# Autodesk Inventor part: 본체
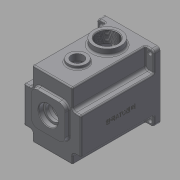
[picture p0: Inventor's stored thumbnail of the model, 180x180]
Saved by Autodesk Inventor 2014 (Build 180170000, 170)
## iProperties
Created: 2016-02
Part Number: 본체
Material: 일반
Document SubType Name: Modeling
Designer: mduedu
Density: 2.71 g/cm^3
Appearance: 기본값
Author: mduedu
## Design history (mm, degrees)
sketch "스케치1"
  geometry: L1 (-47, -47)-(47, -47); L2 (47, -47)-(47, 63); L3 (47, 63)-(-47, 63); L4 (-47, 63)-(-47, -47); 2 further points
  constraints: 8 end point, 2 parallel, 1 horizontal, 1 midpoint, 1 perpendicular, 1 vertical alignment
  dimensions: "d0" = 94 distance of L2.end L3.end; "d155" = 110 distance of L1.end L2.end; "d156" = 47 distance from line of L1 point (0, 0)
extrude "돌출1" new body sketch "스케치1" distance "d2" = 130; taper "d3" = 0 deg
sketch "스케치3"
  geometry: C1 r 40 at (0, 0); 1 further point
  constraints: 1 centre point, 1 coincident
  dimensions: "d9" = 80 diameter of C1
extrude "돌출3" cut sketch "스케치3" distance "d11" = 121; taper "d12" = 0 deg
sketch "스케치4"
  geometry: C1 r 21 at (0, 11); 1 further point
  constraints: 1 centre point, 1 vertical alignment
  dimensions: "d13" = 21 radius of C1; "d15" = 11 distance of point (0, 0) C1.centre
extrude "돌출4" join sketch "스케치4" distance "d16" = 7; taper "d17" = 0 deg
sketch "스케치5"
  geometry: C1 r 15 at (0, -20); 1 further point
  constraints: 1 centre point, 1 vertical alignment
  dimensions: "d18" = 15 radius of C1; "d20" = 20 distance of point (0, 0) C1.centre
extrude "돌출5" join sketch "스케치5" distance "d21" = 7; taper "d22" = 0 deg
sketch "스케치6"
  geometry: L1 (-28, -17)-(28, -17); L2 (28, -17)-(28, 39); L3 (28, 39)-(-28, 39); L4 (-28, 39)-(-28, -17); L5 (-28, -17)-(28, 39); L6 (28, -17)-(-28, 39); C1 r 28 at (0, 11); A1 r 21 centre (0, 11) between (8.978, -7.984) and (-8.978, -7.984) reference; 1 further point
  constraints: 12 end point, 2 midpoint, 2 parallel, 2 tangent, 1 centre point, 1 coincident, 1 horizontal, 1 perpendicular
  dimensions: "d23" = 56 diameter of C1
extrude "돌출6" join sketch "스케치6" distance "d25" = 7; taper "d26" = -3 deg
hole "구멍1" diameter "d29" = 35; stored, may be unused: countersink angle "d33" = 90 deg, drill point angle "d35" = 0 deg; dims "d27" = 10, "d28" = 10, "d30" = 6, "d31" = 4, "d32" = 2, "d34" = 10
hole "구멍2" diameter "d38" = 22; stored, may be unused: countersink angle "d42" = 90 deg, drill point angle "d44" = 0 deg; dims "d36" = 10, "d37" = 10, "d39" = 6, "d40" = 4, "d41" = 2, "d43" = 7
hole "구멍3" diameter "d47" = 19; stored, may be unused: countersink angle "d51" = 90 deg, drill point angle "d53" = 0 deg; dims "d45" = 10, "d46" = 10, "d48" = 6, "d49" = 4, "d50" = 2, "d52" = 1
hole "구멍4" diameter "d56" = 32; stored, may be unused: countersink angle "d60" = 90 deg, drill point angle "d62" = 0 deg; dims "d57" = 6, "d58" = 4, "d59" = 2, "d61" = 8, "d220" = 10, "d221" = 10
hole "구멍5" diameter "d65" = 25; stored, may be unused: countersink angle "d69" = 90 deg, drill point angle "d71" = 0 deg; dims "d63" = 10, "d64" = 10, "d66" = 6, "d67" = 4, "d68" = 2, "d70" = 8
fillet "모깎기2" dims "d73" = 0.3
fillet "모깎기3" dims "d74" = 2
chamfer "모따기1" distance "d75" = 1; stored, may be unused: second distance "d76" = 2, angle "d77" = 45 deg
fillet "모깎기4" dims "d78" = 3
sketch "스케치16"
  geometry: L1 (-23, 32.726)-(23, 32.726); L2 (23, 32.726)-(23, 53); L3 (23, 53)-(-23, 53); L4 (-23, 53)-(-23, 32.726); L5 (-47, 63)-(47, 63) reference; 3 further points
  constraints: 8 end point, 2 parallel, 1 horizontal, 1 midpoint, 1 perpendicular, 1 vertical alignment, 2 other
  dimensions: "d160" = 46 distance of L2.end L3.end; "d163" = 10 distance between parallel lines of L3 L5
extrude "돌출15" cut sketch "스케치16" stored distance "d164" = 10; taper "d165" = 0 deg
fillet "모깎기5" dims "d79" = 2
fillet "모깎기15" dims "d166" = 5
sketch "스케치7"
  geometry: L1 (-23, 48)-(-23, 35.228) reference; L2 (23, 35.228)-(23, 48) reference; L3 (18, 53)-(-18, 53) reference; L4 (47, 63)-(47, -47) reference; L5 (47, -47)-(-47, -47) reference; L6 (-47, -47)-(-47, 63) reference; L7 (-47, 63)-(47, 63) reference; L8 (-26, 48)-(-26, 35.228); L9 (26, 35.228)-(26, 48); L10 (18, 56)-(-18, 56); C1 r 43 at (0, 0); A1 r 5 centre (-18, 48) between (-18, 53) and (-23, 48) reference; A2 r 5 centre (-28, 35.228) between (-24.889, 31.314) and (-23, 35.228) reference; A3 r 40 centre (0, 0) between (-24.889, 31.314) and (24.889, 31.314) reference; A4 r 5 centre (28, 35.228) between (23, 35.228) and (24.889, 31.314) reference; A5 r 5 centre (18, 48) between (23, 48) and (18, 53) reference; A6 r 8 centre (-18, 48) between (-18, 56) and (-26, 48); A7 r 2 centre (-28, 35.228) between (-26.756, 33.662) and (-26, 35.228); A8 r 43 centre (0, 0) between (-26.756, 33.662) and (26.756, 33.662); A9 r 2 centre (28, 35.228) between (26, 35.228) and (26.756, 33.662); A10 r 8 centre (18, 48) between (26, 48) and (18, 56); 1 further point
  constraints: 10 point on circle, 6 centre point, 6 end point, 1 coincident, 7 other
  dimensions: "d80" = 86 diameter of C1; "d167" = 3 distance between parallel lines of L3 L10
extrude "돌출7" cut sketch "스케치7" distance "d83" = 9; taper "d84" = 0 deg
sketch "스케치8" dims "d168" = 36
  geometry: L1 (-36, 4)-(-39.799, 4); L2 (-36, -4)-(-39.799, -4); A1 r 4 centre (-36, 0) between (-36, 4) and (-36, -4); A2 r 40 centre (0, 0) between (-24.889, 31.314) and (24.889, 31.314) reference; A3 r 40 centre (0, 0) between (-39.799, 4) and (-39.799, -4); 2 further points
  constraints: 5 point on circle, 4 end point, 2 centre point, 2 coincident, 2 horizontal alignment, 2 tangent, 1 horizontal, 1 parallel, 2 other
  dimensions: "d169" = 4 radius of A1
extrude "돌출9" join sketch "스케치8" stored distance "d89" = 9; taper "d90" = 0 deg
fillet "모깎기6" dims "d91" = 3.5
node "작업 평면1"
sketch "스케치9"
  geometry: L1 (47, 63)-(33, 63); L2 (33, 63)-(33, 30); L3 (33, 30)-(47, 30); L4 (47, 30)-(47, 63); L5 (47, 63)-(-47, 63) reference; L6 (47, -47)-(47, 63) reference; A1 r 40 centre (0, 0) between (-39.148, -8.214) and (39.148, -8.214) reference; 1 further point
  constraints: 8 end point, 2 parallel, 1 coincident, 1 horizontal, 1 perpendicular
  dimensions: "d95" = 33 distance from line of L2 point (0, 0); "d96" = 30 distance from line of L3 point (0, 0)
extrude "돌출10" cut sketch "스케치9" distance "d97" = 110; taper "d98" = 0 deg
extrude "돌출21" cut sketch "스케치9" stored distance "d217" = 10; taper "d218" = 0 deg
sketch "스케치11" dims "d20" = 20
  geometry: L1 (-40, -40)-(40, -40); L2 (40, -40)-(40, 56); L3 (40, 56)-(-40, 56); L4 (-40, 56)-(-40, -40); L5 (-47, -47)-(47, -47) reference; L6 (47, 63)-(-47, 63) reference; L7 (-47, 63)-(-47, -47) reference; C1 r 3.5 at (-40, 56); C2 r 3.5 at (40, 56); C3 r 3.5 at (40, -40); C4 r 3.5 at (-40, -40); 1 further point
  constraints: 8 end point, 4 centre point, 4 coincident, 3 equal radius, 2 parallel, 1 horizontal, 1 perpendicular
  dimensions: "d109" = 80 distance of L2.end L3.end; "d112" = 7 diameter of C1; "d157" = 7 distance from line of L1.start L5; "d158" = 7 distance between parallel lines of L6 L3; "d159" = 7 distance from line of L7 L3.end
extrude "돌출12" cut sketch "스케치11" stored distance "d113" = 63; taper "d114" = 0 deg
fillet "모깎기7" dims "d115" = 5, "d187" = 5
fillet "모깎기8" dims "d116" = 5
fillet "모깎기18" dims "d219" = 2
fillet "모깎기12" dims "d120" = 2
fillet "모깎기13" dims "d121" = 2
sketch "스케치12"
  geometry: 3 further points
  constraints: 2 horizontal alignment
hole "구멍6" sketch "스케치12" at (36, 0), (-36, 0) diameter "d122" = 3.242; stored, may be unused: countersink angle "d126" = 90 deg, drill point angle "d128" = 120 deg; dims "d123" = 7, "d124" = 4, "d125" = 2, "d127" = 9
fillet "모깎기14" dims "d147" = 10
chamfer "모따기4" distance "d151" = 1; stored, may be unused: second distance "d152" = 2, angle "d153" = 45 deg
sketch "스케치20"
  geometry: L1 (73, -12)-(73, -130) reference; L2 (84, -8)-(77, -8) reference; L3 (84, 0)-(84, -8) reference; L4 (84, 0)-(0, 0) reference; L5 (7, -8)-(0, -8) reference; L6 (11, -130)-(11, -12) reference; L7 (0, -8)-(0, 0) reference; L8 (73, -130)-(11, -130) reference; L9 (42, 0)-(42, -130); C1 r 10 at (42, -89); A1 r 4 centre (77, -12) between (77, -8) and (73, -12) reference; A2 r 4 centre (7, -12) between (11, -12) and (7, -8) reference
  constraints: 2 end point, 1 centre point, 1 midpoint, 1 point on line
  dimensions: "d189" = 20 diameter of C1; "d190" = 41 distance from line of C1.centre L8
extrude "돌출19" cut sketch "스케치20" stored distance "d191" = 10; taper "d192" = 0 deg
sketch "스케치18"
  geometry: C1 r 15 at (42, -89); C2 r 10 at (42, -89) reference; 1 further point
  constraints: 1 centre point, 1 concentric
  dimensions: "d174" = 30 diameter of C1
extrude "돌출17" join sketch "스케치18" distance "d175" = 5; taper "d176" = 0 deg
fillet "모깎기16" dims "d177" = 2
sketch "스케치19"
  geometry: C1 r 10 at (18, 80) reference; C2 r 15 at (18, 80); 1 further point
  constraints: 1 centre point, 1 coincident
  dimensions: "d178" = 30 diameter of C2
extrude "돌출18" cut sketch "스케치19" distance "d181" = 5; taper "d182" = 0 deg
chamfer "모따기5" distance "d183" = 0.5; stored, may be unused: second distance "d184" = 2, angle "d185" = 45 deg
sketch "스케치21"
  geometry: L1 (-12, 14)-(-130, 14) reference; L2 (-8, 0)-(-8, 10) reference; L3 (0, 0)-(0, 100) reference; L4 (-8, 100)-(0, 100) reference; L5 (-8, 74)-(-8, 100) reference; L6 (-130, 70)-(-12, 70) reference; L7 (-130, 14)-(-130, 70) reference; L8 (0, 0)-(-8, 0) reference; L9 (-130, 14)-(-130, 70) reference; L10 (27.4, 42)-(-164.4, 42) reference; A1 r 4 centre (-12, 74) between (-12, 70) and (-8, 74) reference; A2 r 4 centre (-12, 10) between (-8, 10) and (-12, 14) reference; 3 further points
  constraints: 1 coincident, 1 point on line, 1 other
  dimensions: "d222" = 65 distance from line of point (-65, 42) L9
feature "엠보싱2" sketch "스케치21" dims "d20" = 20, "d193" = 0.5, "d194" = 0
sketch "스케치22"
  geometry: L1 (73, -12)-(73, -130) reference; L2 (84, -8)-(77, -8) reference; L3 (84, 0)-(84, -8) reference; L4 (84, 0)-(0, 0) reference; L5 (7, -8)-(0, -8) reference; L6 (11, -130)-(11, -12) reference; L7 (0, -8)-(0, 0) reference; L8 (73, -130)-(11, -130) reference; L9 (42, -130)-(42, 0); C1 r 17 at (42, -89) reference; C2 r 22.5 at (42, -40); A1 r 4 centre (77, -12) between (77, -8) and (73, -12) reference; A2 r 4 centre (7, -12) between (11, -12) and (7, -8) reference
  constraints: 2 end point, 1 centre point, 1 midpoint, 1 point on line
  dimensions: "d195" = 45 diameter of C2; "d197" = 40 distance from line of C2.centre L4
extrude "돌출20" join sketch "스케치22" distance "d198" = 10; taper "d199" = 0 deg
fillet "모깎기17" dims "d200" = 3
hole "구멍7" diameter "d203" = 33.376; stored, may be unused: countersink angle "d207" = 90 deg, drill point angle "d209" = 118 deg; dims "d204" = 6, "d205" = 4, "d206" = 2, "d208" = 8, "d223" = 10, "d224" = 10
chamfer "모따기6" distance "d210" = 1; stored, may be unused: second distance "d211" = 2, angle "d212" = 45 deg
fillet "모깎기19" dims "d225" = 2
node "솔리드1"
pattern_circular "원형 패턴1" dims angle "d93" = 360 deg
mirror "대칭1"
mirror "대칭2"
node "투영된 루프1"
node "투영된 루프2"
node "투영된 루프3"
node "절단 모서리 투영3"
